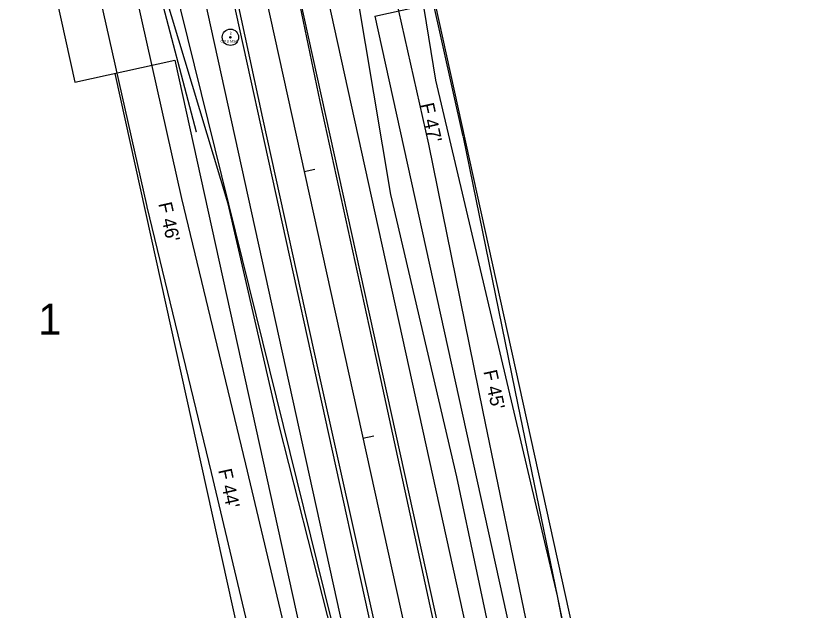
# Model space of a CAD drawing. Extents: x 2519952 to 2531965, y 848341 to 887632.
# Drawn here: x 2530907.4 to 2531201.4, y 852156.1 to 852373.9 of the extents above; entities that cross this region are included whole.
import ezdxf

# ---------------------------------------------------------------- set-up
doc = ezdxf.new("R2010")
doc.units = 0
for name, color, linetype in [('RD_EV_JW', 7, 'Continuous'), ('RD_EX_DV_Prop', 7, 'Continuous'), ('RD_EX_DV_TX_Prop', 7, 'Continuous'), ('RD_EX_H2O', 7, 'Continuous'), ('RD_EX_Road', 7, 'Continuous'), ('RD_EX_RW', 7, 'Continuous'), ('RD_EX_VEG', 7, 'Continuous'), ('RD_HC_Cl', 7, 'Continuous'), ('RD_HC_Data', 7, 'Continuous'), ('RD_HC_Data_Tic', 7, 'Continuous'), ('RD_HC_txCode', 7, 'Continuous'), ('RD_PD_CstnLmt', 7, 'Continuous'), ('RD_PD_DR_ErosCtrl', 7, 'Continuous'), ('RD_PD_Final_TrvlWay', 7, 'Continuous'), ('RD_PD_GR', 7, 'Continuous'), ('RD_PD_RW', 7, 'Continuous'), ('RD_PD_TX_CstnLmt', 7, 'Continuous'), ('RD_SMD_Locator', 7, 'Continuous')]:
    doc.layers.add(name, color=color, linetype=linetype)

msp = doc.modelspace()

# ---------------------------------------------------------------- linework, layer by layer
at = {"layer": 'RD_EV_JW'}
for points in [[(2531125.63, 851940.25), (2531091.18, 852099.75), (2531068.77, 852205.2), (2531044.69, 852308.54), (2531029.19, 852401.02), (2531017.83, 852485.31), (2530998.59, 852494.65)], [(2531008.51, 851859.82), (2531048.19, 851907.85), (2531066.71, 851925.01), (2531063.54, 851972.89), (2531028.5, 852126.6), (2531003.69, 852223.96), (2530985.02, 852305.06), (2530961.67, 852382.94), (2530951.5, 852421.65), (2530941.26, 852459.07)]]:
    msp.add_lwpolyline(points, dxfattribs=at)
at = {"layer": 'RD_EX_DV_Prop'}
for p, q in [((2530864.42, 852642.64), (2530928.94, 852349.66)), ((2531038.81, 852373.85), (2531146.33, 851885.55)), ((2530928.94, 852349.66), (2530965.56, 852357.72)), ((2530965.56, 852357.72), (2531073.09, 851869.42)), ((2530965.56, 852357.72), (2531073.09, 851869.42))]:
    msp.add_line(p, q, dxfattribs=at)
at = {"layer": 'RD_EX_H2O'}
msp.add_lwpolyline([(2530973.5, 852331.3), (2530944.44, 852441.73), (2530937.03, 852452.89), (2530951.23, 852484.72), (2530998.33, 852495.88), (2531008.59, 852496.17)], dxfattribs=at)
at = {"layer": 'RD_EX_Road'}
for p, q in [((2531018.73, 852342.63), (2530998.34, 852441.09)), ((2530997.76, 852336.47), (2530976.23, 852436.08)), ((2531039.32, 852248.88), (2531018.73, 852342.63)), ((2531018.1, 852243.96), (2530997.76, 852336.47)), ((2531060.27, 852152.35), (2531039.32, 852248.88)), ((2531039.87, 852146.34), (2531018.1, 852243.96))]:
    msp.add_line(p, q, dxfattribs=at)
at = {"layer": 'RD_EX_RW'}
for p, q in [((2530864.42, 852642.64), (2530928.94, 852349.65)), ((2531038.81, 852373.85), (2531075.43, 852381.91)), ((2531038.81, 852373.85), (2531146.33, 851885.55)), ((2530928.94, 852349.65), (2530965.56, 852357.72)), ((2530965.56, 852357.72), (2531073.09, 851869.42))]:
    msp.add_line(p, q, dxfattribs=at)
at = {"layer": 'RD_EX_VEG'}
for points in [[(2530980.99, 851808.39), (2531073.01, 851889.15), (2531025.34, 852142.99), (2530952.71, 852437.06), (2530949.82, 852466.79)], [(2531179.51, 851966.14), (2531146.93, 851949.23), (2531105.69, 852161.62), (2531061.1, 852350.33), (2531043.12, 852460.73)]]:
    msp.add_lwpolyline(points, dxfattribs=at)
at = {"layer": 'RD_HC_Cl'}
msp.add_line((2530821.93, 853184.38), (2531378.52, 850656.73), dxfattribs=at)
at = {"layer": 'RD_HC_Data'}
for radius in [3, 0.282]:
    msp.add_circle((2530985.9, 852366.09), radius, dxfattribs=at)
at = {"layer": 'RD_HC_Data_Tic'}
for p, q in [((2531012.94, 852316.95), (2531016.84, 852317.81)), ((2531034.44, 852219.29), (2531038.35, 852220.15))]:
    msp.add_line(p, q, dxfattribs=at)
at = {"layer": 'RD_PD_CstnLmt'}
for p, q in [((2531036.51, 852424.54), (2531058.37, 852326.96)), ((2530946.09, 852404.63), (2530967.94, 852307.04)), ((2531058.37, 852326.96), (2531078.37, 852228.97)), ((2530967.94, 852307.04), (2530991.47, 852209.83)), ((2531078.37, 852228.97), (2531098.63, 852131.03)), ((2530991.47, 852209.83), (2531014.55, 852112.52))]:
    msp.add_line(p, q, dxfattribs=at)
at = {"layer": 'RD_PD_DR_ErosCtrl'}
for p, q in [((2531049.2, 852427.38), (2531071.06, 852329.8)), ((2530933.4, 852401.79), (2530955.25, 852304.2)), ((2531071.11, 852329.56), (2531091.11, 852231.57)), ((2530955.3, 852303.99), (2530978.83, 852206.77)), ((2531091.1, 852231.6), (2531111.36, 852133.66)), ((2530978.82, 852206.83), (2531001.9, 852109.52))]:
    msp.add_line(p, q, dxfattribs=at)
at = {"layer": 'RD_PD_Final_TrvlWay'}
for p, q in [((2530922.51, 852783.42), (2531196.7, 851538.25)), ((2530899.07, 852778.26), (2531173.26, 851533.09))]:
    msp.add_line(p, q, dxfattribs=at)
at = {"layer": 'RD_PD_GR'}
for p, q in [((2531012.65, 852420.57), (2531171.25, 851700.32)), ((2531077.2, 851922.8), (2530969.68, 852411.11))]:
    msp.add_line(p, q, dxfattribs=at)
at = {"layer": 'RD_PD_RW'}
for p, q in [((2531060.78, 852378.69), (2531168.31, 851890.39)), ((2530943.59, 852352.88), (2531078, 851742.5))]:
    msp.add_line(p, q, dxfattribs=at)
at = {"layer": 'RD_SMD_Locator'}
for centre in [(2530985.9, 852366.09), (2531061.1, 852350.33), (2531018.73, 852342.63), (2530997.76, 852336.47), (2530973.5, 852331.3), (2531044.69, 852308.54), (2530985.02, 852305.06), (2531039.32, 852248.88), (2531018.1, 852243.96), (2531003.69, 852223.96), (2531068.77, 852205.2), (2531105.69, 852161.62)]:
    msp.add_circle(centre, 0.001, dxfattribs=at)

# ---------------------------------------------------------------- texts
at = {"layer": 'RD_EX_DV_TX_Prop'}
msp.add_text('1', height=11.32, dxfattribs=at).set_placement((2530915.54, 852257.25))
at = {"layer": 'RD_HC_txCode'}
for s, p in [('2', (2530985.62, 852367.09)), ('CP 2 MSC', (2530982.27, 852364.09))]:
    msp.add_text(s, height=1, dxfattribs=at).set_placement(p)
at = {"layer": 'RD_PD_CstnLmt'}
for s, p in [("F 46'", (2530959.45, 852305.18)), ("F 44'", (2530981.38, 852207.61))]:
    msp.add_text(s, height=5, rotation=282.4185, dxfattribs=at).set_placement(p)
at = {"layer": 'RD_PD_TX_CstnLmt'}
for s, p in [("F 47'", (2531055.42, 852341.52)), ("F 45'", (2531078.51, 852243.78))]:
    msp.add_text(s, height=5, rotation=282.4185, dxfattribs=at).set_placement(p)

doc.saveas('drawing.dxf')
